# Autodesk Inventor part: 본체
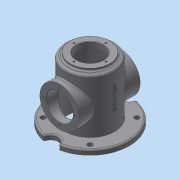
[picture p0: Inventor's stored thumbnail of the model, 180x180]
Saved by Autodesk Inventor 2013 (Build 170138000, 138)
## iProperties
Created: 2018-04
Part Number: 본체
Material: 일반
Document SubType Name: Modeling
Designer: dgall
Density: 1 g/cm^3
Author: dgall
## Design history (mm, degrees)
sketch "스케치1"
  geometry: C1 r 50 at (0, 0); 1 further point
  constraints: 1 centre point, 1 coincident
  dimensions: "d0" = 100 diameter of C1
extrude "돌출1" new body sketch "스케치1" distance "d1" = 110; taper "d2" = 0 deg
fillet "모깎기1" dims "d3" = 5
sketch "스케치2"
  geometry: C1 r 45 at (0, 0) reference; C2 r 50 at (0, 0) reference; C3 r 80 at (0, 0)
  constraints: 1 centre point, 1 coincident
  dimensions: "d5" = 160 diameter of C3
extrude "돌출2" join sketch "스케치2" distance "d6" = 10; taper "d7" = 0 deg
sketch "스케치3"
  geometry: C1 r 45 at (0, 0) reference; C2 r 80 at (0, 0) reference; C3 r 50 at (0, 0)
  constraints: 1 centre point, 1 coincident
  dimensions: "d8" = 100 diameter of C3
extrude "돌출3" join sketch "스케치3" distance "d9" = 8; taper "d10" = 0 deg
sketch "스케치4"
  geometry: C1 r 45 at (0, 0) reference; C2 r 40 at (0, 0)
  constraints: 1 centre point, 1 coincident
  dimensions: "d11" = 80 diameter of C2
extrude "돌출4" join sketch "스케치4" distance "d12" = 5; taper "d13" = 0 deg
hole "구멍1" diameter "d16" = 54; stored, may be unused: countersink angle "d20" = 90 deg, drill point angle "d22" = 0 deg; dims "d17" = 6, "d18" = 4, "d19" = 2, "d21" = 13, "d87" = 10, "d88" = 10
node "작업 평면1"
sketch "스케치5"
  geometry: L1 (-80, -10)-(80, -10) reference; C1 r 40 at (0, 50); 1 further point
  constraints: 1 centre point, 1 vertical alignment
  dimensions: "d24" = 80 diameter of C1; "d25" = 60 distance from line of C1.centre L1
extrude "돌출5" join sketch "스케치5" stored distance "d26" = 5; taper "d27" = 0 deg
sketch "스케치6" dims "d28" = 65
  geometry: L1 (0, 0)-(0, -32.5); C1 r 40 at (0, 0) reference; 2 further points
  constraints: 2 coincident, 2 end point, 1 vertical, 1 vertical alignment, 2 other
hole "구멍2" sketch "스케치6" at (0, -32.5) diameter "d29" = 3.242; stored, may be unused: countersink angle "d33" = 90 deg, drill point angle "d35" = 118 deg; dims "d30" = 8, "d31" = 4, "d32" = 2, "d34" = 10
sketch "스케치7" dims "d48" = 160, "d50" = 135
  geometry: L1 (0, 0)-(0, -80); L2 (0, 0)-(0, -80); L3 (0, 0)-(-47.73, -47.73); C1 r 50 at (0, 0) reference; C2 r 15 at (0, -80); C3 r 5 at (-47.73, -47.73)
  constraints: 6 end point, 4 coincident, 2 centre point, 1 collinear, 1 vertical, 1 vertical alignment, 5 other
  dimensions: "d49" = 30 diameter of C2; "d51" = 45 deg angle of L3 L2; "d52" = 10 diameter of C3
extrude "돌출6" cut sketch "스케치7" distance "d53" = 10; taper "d54" = 0 deg
extrude "돌출7" cut sketch "스케치7" distance "d55" = 10; taper "d56" = 0 deg
sketch "스케치8" dims "d60" = 65
  geometry: L1 (0, 0)-(0, 32.5); C1 r 40 at (0, 0) reference; 1 further point
  constraints: 2 coincident, 2 end point, 1 vertical, 1 vertical alignment, 2 other
hole "구멍4" sketch "스케치8" at (0, 32.5) diameter "d61" = 3.242; stored, may be unused: countersink angle "d65" = 90 deg, drill point angle "d67" = 118 deg; dims "d62" = 8, "d63" = 4, "d64" = 2, "d66" = 10
node "작업 평면4"
sketch "스케치9"
  geometry: L1 (78.594, 0)-(-78.594, 0) reference; L2 (-78.594, -10)-(78.594, -10) reference; 3 further points
  constraints: 1 midpoint, 1 vertical alignment, 1 other
  dimensions: "d72" = 70 distance from line of point (0, 60) L2
feature "엠보싱1" sketch "스케치9" dims "d73" = 0.5, "d74" = 0
chamfer "모따기1" distance "d78" = 1; stored, may be unused: second distance "d79" = 2, angle "d80" = 45 deg
sketch "스케치10"
  geometry: L1 (-28, 115)-(-27, 114) reference; L2 (-27, 114)-(-27, 102) reference; L3 (-30.879, 105)-(-30.879, 115) reference; L4 (-30.879, 115)-(-28, 115) reference; L5 (27, 114)-(28, 115) reference; L6 (28, 115)-(30.879, 115) reference; L7 (30.879, 115)-(30.879, 105) reference; L8 (27, 102)-(27, 114) reference; L9 (-51.026, 17.5)-(-52, 19.121) reference; L10 (-62, 15.879)-(-52, 15.879) reference; L11 (-45, -18)-(-49, -18) reference; L12 (50, -17)-(49, -18) reference; L13 (50, -10)-(50, -17) reference; L14 (-50, -10)-(-65, -10) reference; L15 (-65, -10)-(-65, 0) reference; L16 (-65, 0)-(-50, 0) reference; L17 (-50, 10)-(-62, 10) reference; L18 (-62, 10)-(-62, 15.879) reference; L19 (-52, 19.121)-(-62, 19.121) reference; L20 (-52, 15.879)-(-51.026, 17.5) reference; L21 (-52, 80.879)-(-51.026, 82.5) reference; L22 (-51.026, 82.5)-(-52, 84.121) reference; L23 (-52, 84.121)-(-62, 84.121) reference; L24 (-62, 84.121)-(-62, 90) reference; L25 (-62, 90)-(-50, 90) reference; L26 (-50, 90)-(-50, 105) reference; L27 (-45, 110)-(-40, 110) reference; L28 (-40, 110)-(-40, 115) reference; L29 (-40, 115)-(-34.121, 115) reference; L30 (-34.121, 115)-(-34.121, 105) reference; L31 (-62, 80.879)-(-52, 80.879) reference; L32 (52, 19.121)-(51.026, 17.5) reference; L33 (51.026, 17.5)-(52, 15.879) reference; L34 (52, 15.879)-(62, 15.879) reference; L35 (62, 15.879)-(62, 10) reference; L36 (62, 10)-(50, 10) reference; L37 (50, 0)-(65, 0) reference; L38 (65, 0)-(65, -10) reference; L39 (65, -10)-(50, -10) reference; L40 (-50, -17)-(-50, -10) reference; L41 (-49, -18)-(-50, -17) reference; L42 (49, -18)-(45, -18) reference; L43 (62, 19.121)-(52, 19.121) reference; L44 (51.026, 82.5)-(52, 80.879) reference; L45 (52, 80.879)-(62, 80.879) reference; L46 (62, 80.879)-(62, 19.121) reference; L47 (34.121, 105)-(34.121, 115) reference; L48 (34.121, 115)-(40, 115) reference; L49 (40, 115)-(40, 110) reference; L50 (40, 110)-(45, 110) reference; L51 (50, 105)-(50, 90) reference; L52 (50, 90)-(62, 90) reference; L53 (62, 90)-(62, 84.121) reference; L54 (62, 84.121)-(52, 84.121) reference; L55 (52, 84.121)-(51.026, 82.5) reference; L56 (45, -18)-(45, 0) reference; L57 (45, 0)-(-45, 0) reference; L58 (-45, 0)-(-45, -18) reference; L59 (-62, 19.121)-(-62, 80.879) reference; L60 (-34.121, 105)-(-32.5, 104.026) reference; L61 (-32.5, 104.026)-(-30.879, 105) reference; L62 (-27, 102)-(27, 102) reference; L63 (30.879, 105)-(32.5, 104.026) reference; L64 (32.5, 104.026)-(34.121, 105) reference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; A1 r 5 centre (-45, 105) between (-45, 110) and (-50, 105) reference; A2 r 5 centre (45, 105) between (50, 105) and (45, 110) reference; 1 further point
  node "절단 모서리 투영1"
sketch "스케치11"
  geometry: C1 r 45 at (0, 0) reference; C2 r 49 at (0, 0) reference; C3 r 45 at (0, 0)
  constraints: 1 centre point, 1 coincident
  dimensions: "d83" = 90 diameter of C3
extrude "돌출8" cut sketch "스케치11" distance "d85" = 120; taper "d86" = 0 deg
hole "구멍5" diameter "d91" = 54; stored, may be unused: countersink angle "d95" = 90 deg, drill point angle "d97" = 118 deg; dims "d89" = 10, "d90" = 10, "d92" = 8, "d93" = 4, "d94" = 2, "d96" = 10
hole "구멍6" diameter "d100" = 54; stored, may be unused: countersink angle "d104" = 90 deg, drill point angle "d106" = 118 deg; dims "d98" = 10, "d99" = 10, "d101" = 8, "d102" = 4, "d103" = 2, "d105" = 10
chamfer "모따기2" distance "d108" = 1; stored, may be unused: second distance "d109" = 2, angle "d110" = 45 deg
sketch "스케치12"
  geometry: L1 (-51.026, 17.5)-(-52, 19.121) reference; L2 (-52, 19.121)-(-62, 19.121) reference; L3 (-62, 19.121)-(-62, 22) reference; L4 (-62, 22)-(-61, 23) reference; L5 (-61, 23)-(-45, 23) reference; L6 (-45, 23)-(-45, -18) reference; L7 (-45, -18)-(-49, -18) reference; L8 (-49, -18)-(-50, -17) reference; L9 (-50, -17)-(-50, -10) reference; L10 (-50, -10)-(-65, -10) reference; L11 (-65, -10)-(-65, 0) reference; L12 (-65, 0)-(-50, 0) reference; L13 (-50, 10)-(-62, 10) reference; L14 (-62, 10)-(-62, 15.879) reference; L15 (-62, 15.879)-(-52, 15.879) reference; L16 (-52, 15.879)-(-51.026, 17.5) reference; L17 (-52, 80.879)-(-51.026, 82.5) reference; L18 (-51.026, 82.5)-(-52, 84.121) reference; L19 (-52, 84.121)-(-62, 84.121) reference; L20 (-62, 84.121)-(-62, 90) reference; L21 (-62, 90)-(-50, 90) reference; L22 (-50, 90)-(-50, 105) reference; L23 (-45, 110)-(-40, 110) reference; L24 (-40, 110)-(-40, 115) reference; L25 (-40, 115)-(-34.121, 115) reference; L26 (-34.121, 115)-(-34.121, 105) reference; L27 (-34.121, 105)-(-32.5, 104.026) reference; L28 (-32.5, 104.026)-(-30.879, 105) reference; L29 (-30.879, 105)-(-30.879, 115) reference; L30 (-30.879, 115)-(-28, 115) reference; L31 (-28, 115)-(-27, 114) reference; L32 (-27, 114)-(-27, 102) reference; L33 (-27, 102)-(-45, 102) reference; L34 (-45, 77)-(-61, 77) reference; L35 (-61, 77)-(-62, 78) reference; L36 (-62, 78)-(-62, 80.879) reference; L37 (-62, 80.879)-(-52, 80.879) reference; L38 (52, 19.121)-(51.026, 17.5) reference; L39 (51.026, 17.5)-(52, 15.879) reference; L40 (52, 15.879)-(62, 15.879) reference; L41 (62, 15.879)-(62, 10) reference; L42 (62, 10)-(50, 10) reference; L43 (50, 0)-(65, 0) reference; L44 (65, 0)-(65, -10) reference; L45 (65, -10)-(50, -10) reference; L46 (50, -10)-(50, -17) reference; L47 (50, -17)-(49, -18) reference; L48 (49, -18)-(45, -18) reference; L49 (45, -18)-(45, 23) reference; L50 (45, 23)-(61, 23) reference; L51 (61, 23)-(62, 22) reference; L52 (62, 22)-(62, 19.121) reference; L53 (62, 19.121)-(52, 19.121) reference; L54 (51.026, 82.5)-(52, 80.879) reference; L55 (52, 80.879)-(62, 80.879) reference; L56 (62, 80.879)-(62, 78) reference; L57 (62, 78)-(61, 77) reference; L58 (61, 77)-(45, 77) reference; L59 (45, 102)-(27, 102) reference; L60 (27, 102)-(27, 114) reference; L61 (27, 114)-(28, 115) reference; L62 (28, 115)-(30.879, 115) reference; L63 (30.879, 115)-(30.879, 105) reference; L64 (30.879, 105)-(32.5, 104.026) reference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; A1 r 5 centre (-45, 105) between (-45, 110) and (-50, 105) reference; A2 r 5 centre (45, 105) between (50, 105) and (45, 110) reference; 1 further point
  node "절단 모서리 투영2"
fillet "모깎기6" dims "d111" = 3
fillet "모깎기7" dims "d112" = 3
node "솔리드1"
pattern_circular "원형 패턴1" dims angle "d37" = 360 deg
mirror "대칭1"
pattern_circular "원형 패턴2" dims angle "d58" = 360 deg
mirror "대칭2"
pattern_circular "원형 패턴3" dims angle "d69" = 360 deg
node "작업 평면2"
node "작업 평면3"
other parameters: "d23" = 62
